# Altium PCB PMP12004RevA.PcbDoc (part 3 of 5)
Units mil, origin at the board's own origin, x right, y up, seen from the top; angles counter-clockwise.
Board outline 5500 x 4500 mil, 6 copper layers (Top Layer, GND, Signal Layer 1, Signal Layer 2, PWR Split, Bottom Layer), stack 0 mil thick; 355 components, 130 nets, 833 pads, 904 vias.
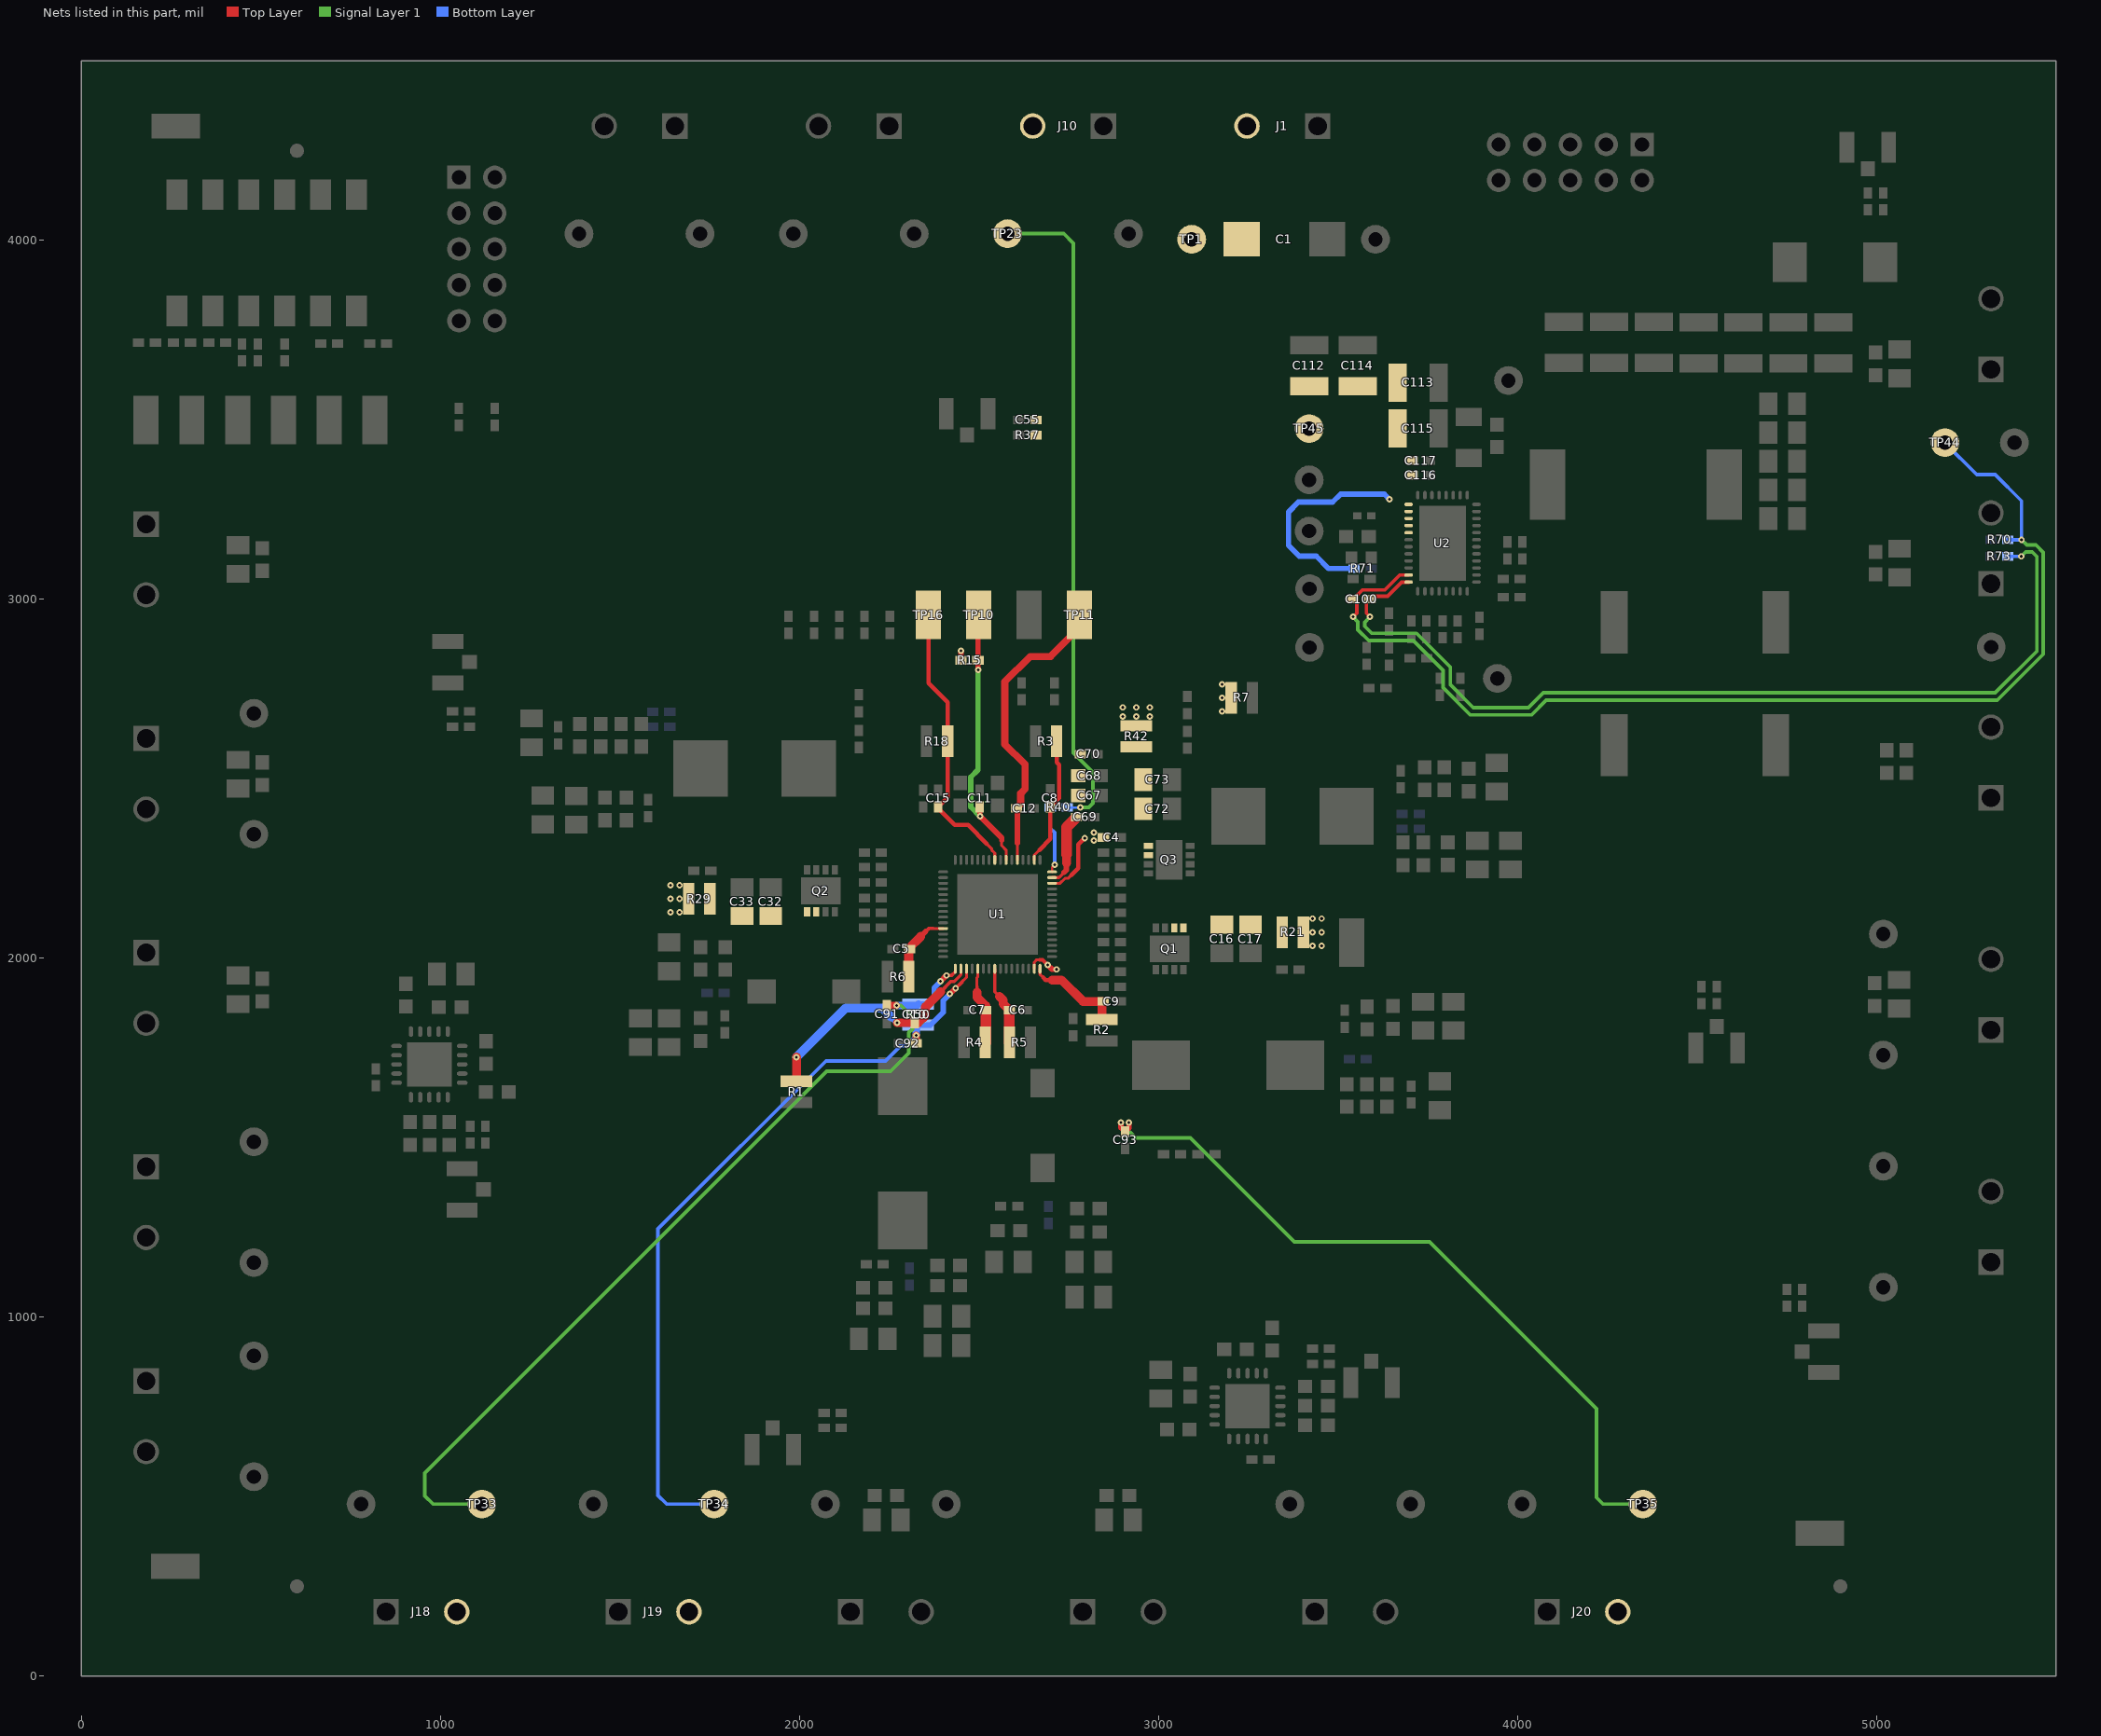
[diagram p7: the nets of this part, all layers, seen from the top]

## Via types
v1: diameter 18, hole 8, Top Layer to Bottom Layer, tented both sides, 835 vias
v2: diameter 19.68, hole 8.01, Top Layer to Bottom Layer, tented bottom, 42 vias
v3: diameter 18, hole 8.01, Top Layer to Bottom Layer, tented bottom, 27 vias

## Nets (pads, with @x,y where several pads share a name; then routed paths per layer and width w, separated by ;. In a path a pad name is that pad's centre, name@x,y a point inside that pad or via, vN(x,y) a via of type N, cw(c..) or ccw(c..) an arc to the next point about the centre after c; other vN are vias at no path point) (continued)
SWA1: C93.1 J20.2 TP35.1 U1.31 | length 2186.4
  Top Layer w8: U1.31@2654.36,1970.89 2654.36,1989.13 2661.07,1995.85 2669.31,1995.85
  Top Layer w10: 2669.31,1995.85 2677.19,1995.85 v1(2691.55,1981.49)
  Top Layer w15: v1(2691.55,1981.49) 2704.12,1968.92 v1(2716.36,1968.92) ; v1(2895.82,1542.6) 2895.82,1528.2 C93.1@2907.42,1516.59 2917.93,1527.11 v1(2917.93,1542.6)
  Signal Layer 1 w10: v1(2917.93,1542.6) 2917.93,1518.97 2937.72,1499.18 3088.85,1499.18 3378.39,1209.64 3755.14,1209.64 4220.11,744.67 4220.11,497.37 4238.48,479 TP35.1@4349.68,479
SWB1: C91.1 J18.2 R50.2 TP33.1 U1.17 | length 2479.3
  Top Layer w8: 2427.02,1955.33 2433.88,1962.19 U1.17@2433.88,1970.89
  Top Layer w10: v1(2409.31,1952.15) 2423.84,1952.15 2427.02,1955.33
  Top Layer w15: v1(2393.18,1936.12) 2393.28,1936.12 v1(2409.31,1952.15)
  Top Layer w20: C91.1@2243.42,1868.22 v1(2270.31,1868.22)
  Signal Layer 1 w10: TP33.1@1115.43,479 979.4,479 956.35,502.05 956.35,565.48 2075.81,1684.94 2253.51,1684.94 2304.61,1736.04 2304.61,1792.51 2314.43,1802.34 2314.43,1836.81 2283.03,1868.22 v1(2270.31,1868.22)
  Bottom Layer w15: R50.2@2330.92,1872.59 2353.74,1872.59 2375.01,1893.87 2375.01,1917.95 v1(2393.18,1936.12)
  Bottom Layer w20: v1(2270.31,1868.22) 2326.54,1868.22 R50.2@2330.92,1872.59
SWB2: C92.1 J19.2 R50.1 TP34.1 U1.19 | length 2137.8
  Top Layer w8: 2452.26,1933.61 2465.38,1946.72 U1.19@2465.38,1970.89
  Top Layer w10: v1(2434.98,1916.32) 2452.26,1933.61
  Top Layer w15: v1@2418.95,1900.29 v1(2434.98,1916.32)
  Top Layer w20: C92.1@2325.42,1762.59 v1(2325.42,1785.58)
  Bottom Layer w10: TP34.1@1762.28,479 1630.53,479 1606.06,503.47 1606.06,1246.03 2073.74,1713.71 2239.86,1713.71 2281.23,1755.08 2294.92,1755.08 v1(2325.42,1785.58)
  Bottom Layer w15: R50.1@2330.92,1813.54 2364.74,1813.54 2400.51,1849.31 2400.51,1881.96 v1(2418.85,1900.29)
  Bottom Layer w20: v1(2325.42,1785.58) 2325.42,1808.04 R50.1@2330.92,1813.54
V5ANA: C15.1 R18.1 TP16.1 U1.57 | length 802.7
  Top Layer w8: 2522.45,2318.5 2535.22,2305.73 2535.22,2301.82 2544.12,2292.92 U1.57@2544.12,2274.04
  Top Layer w12: TP16.1@2359.42,2956.59 2359.42,2766.39 2412.95,2712.86 R18.1@2412.95,2604.59 2412.95,2448.13 C15.1@2386.42,2421.59 2386.42,2417.53 2432.79,2371.16 2469.79,2371.16 2522.45,2318.5
VIN1: C16.1 C17.1 Q1.1 Q1.2 R21.2
VIN2: C32.1 C33.1 Q2.1 Q2.2 R29.2
VIN3: C5.1 R6.2 U1.11 | length 196.4
  Top Layer w8: 2372.69,2083.1 U1.11@2400.42,2083.1
  Top Layer w10: 2351.94,2074.67 2360.36,2083.1 2372.69,2083.1
  Top Layer w15: 2337.83,2060.57 2351.94,2074.67
  Top Layer w25: R6.2@2304.42,1948.59 2304.42,2022.59 C5.1@2307.42,2025.59 ; C5.1@2305.14,2027.88 2337.83,2060.57
VIN4: C6.1 R5.2 U1.24 | length 217.7
  Top Layer w8: 2544.12,1939.57 U1.24@2544.12,1970.89
  Top Layer w10: 2544.12,1939.57 2544.12,1906.64 2553.82,1896.93
  Top Layer w25: 2556.86,1893.71 2567.71,1882.87 2567.71,1872.68 C6.1@2584.8,1855.59
  Top Layer w30: C6.1@2584.8,1855.59 2584.89,1855.5 R5.2@2584.89,1765.59
VIN5: C7.1 R4.2 U1.21 | length 216.3
  Top Layer w8: 2494.62,1920.81 2494.62,1945.73 2496.87,1947.98 U1.21@2496.87,1970.89
  Top Layer w10: 2494.62,1905.38 2494.62,1920.81
  Top Layer w25: 2494.62,1905.38 2494.62,1891.78 2519.04,1867.36 C7.1@2519.04,1855.59
  Top Layer w30: R4.2@2519.04,1765.59 C7.1@2519.04,1855.59
VIN6: C72.1 C73.1 Q3.1 Q3.2 R42.2
VINLDOA2_A3: C8.1 R3.2 U1.50 | length 361.9
  Top Layer w8: U1.50@2654.36,2274.04 2654.36,2287.97 2668.4,2302.02
  Top Layer w12: 2668.4,2302.02 2698.8,2332.41 C8.1@2698.8,2421.97 2723.25,2446.43 2723.25,2539.06 2716.42,2545.89 R3.2@2716.42,2604.59
VINSWA1: C9.1 R2.2 U1.32 | length 270
  Top Layer w8: U1.32@2670.1,1970.89 2670.1,1954.81 2678.74,1946.18
  Top Layer w12: 2678.74,1946.18 2685.35,1939.57 2703.84,1939.57
  Top Layer w25: 2703.84,1939.57 2729.85,1939.57 2789.82,1879.59 2842.42,1879.59 R2.2@2842.42,1829.12
VINSWB: C10.1 R1.2 U1.18 | length 685.7
  Top Layer w8: 2437.49,1941.65 2449.63,1953.79 U1.18@2449.63,1970.89
  Top Layer w10: 2392.86,1906.29 2421.74,1935.18 2431.01,1935.18 2437.49,1941.65
  Top Layer w23: v1(2272.14,1819.97) C10.1@2320.92,1819.97
  Top Layer w25: R1.2@1991.92,1657.29 v1(1991.92,1724.64) ; C10.1@2320.92,1819.97 2330.92,1819.97 2350.9,1839.96 2350.9,1864.34 2392.86,1906.29
  Bottom Layer w18: 2255.92,1836.19 v1(2272.14,1819.97)
  Bottom Layer w25: v1(1991.92,1724.64) 2128.72,1861.45 2230.66,1861.45 2255.92,1836.19
VINVTT: C4.1 R7.2 U1.46 | length 182.2
  Top Layer w8: U1.46@2703.57,2209.08 2726.04,2209.08 2739.43,2222.48 2748.45,2222.48 2757.46,2231.49
  Top Layer w12: 2757.46,2231.49 2776.71,2250.74 2776.71,2316.9 v1(2794.87,2335.05)
  other v1: 2819.74,2327.83 2819.74,2349.95 3177.23,2687.68 3177.23,2725.68 3177.23,2763.68
VOUTS+: C100.1 R70.1 TP44.1 U2.31 | length 3174.1
  Top Layer w10: v1(3542.38,2951.16) 3552.64,2961.42 3552.64,2990.26 C100.1@3542.38,3000.52 3568.19,3026.33 3630.64,3026.33 3672.11,3067.8 U2.31@3696.98,3067.8
  Signal Layer 1 w10: v1(3542.38,2951.16) 3555.76,2937.78 3555.76,2915.44 3585.98,2885.21 3709.96,2885.21 3792.76,2802.41 3792.76,2754.12 3868.65,2678.22 4039.42,2678.22 4080.03,2718.83 5336.66,2718.83 5465,2847.17 5465,3131.2 5444.56,3151.65 5418.86,3151.65 v1(5404.3,3166.2)
  Bottom Layer w10: TP44.1@5191.13,3436.89 5190.73,3436.49 5279.58,3347.63 5331.15,3347.63 5404.3,3274.48 v1(5404.3,3166.2) R70.1@5366.3,3166.2
VOUTS-: C100.2 R73.1 U2.32 | length 2631.6
  Top Layer w10: v1(3589.62,2951.16) 3579.36,2961.42 3579.36,2990.26 C100.2@3589.62,3000.52 3597.89,3008.78 3638.49,3008.78 3677.81,3048.11 U2.32@3696.98,3048.11
  Signal Layer 1 w10: v1(3589.62,2951.16) 3574.94,2936.48 3574.94,2924.96 3594.47,2905.44 3718.54,2905.44 3813.35,2810.63 3813.35,2761.89 3876.69,2698.55 4030.61,2698.55 4072.22,2740.16 5331.44,2740.16 5447.23,2855.95 5447.23,3118.84 5434.11,3131.97 5416.23,3131.97 v1(5404.05,3119.79)
  Bottom Layer w10: R73.1@5366.04,3119.79 v1(5404.05,3119.79)
VREF: C12.1 TP11.1 U1.53 | length 836.7
  Top Layer w8: U1.53@2607.11,2274.04 2607.11,2320.76
  Top Layer w15: C12.1@2604.17,2417.59 2607.11,2414.66 2607.11,2320.76
  Top Layer w20: C12.1@2604.17,2417.59 2616.19,2429.61 2616.19,2459.2 2628.39,2471.4 2628.39,2540.03 2571.86,2596.56 2571.86,2770.27 2642.52,2840.93 2699.11,2840.93 2780.42,2922.24 TP11.1@2780.42,2956.59
VSYS: C1.1 C112.1 C113.1 C114.1 C115.1 C116.1 C117.1 J1.2 R15.2 R21.1 R29.1 R42.1 R71.1 TP1.1 TP45.1 U2.21 U2.22 U2.23 U2.24 U2.25 | length 637.9
  Top Layer w15: R15.2@2450.26,2830.1 v1(2450.26,2856.61)
  Bottom Layer w15: R71.1@3545.31,3085.81 3473.73,3085.81 3439.38,3120.17 3392.48,3120.17 3362.22,3150.43 3362.22,3243.19 3389.86,3270.83 3485.07,3270.83 3507.73,3293.49 3629.06,3293.49 v1(3643.98,3278.57)
  other v1: 3429.35,2034.59 3454.76,2034.59 3429.35,2072.59 3454.76,2072.59 3429.35,2110.59 3454.76,2110.59 1640.55,2127.59 1665.96,2127.59 1640.55,2165.59 1665.96,2165.59 1640.55,2203.59 1665.96,2203.59 2900.42,2673.53 2938.42,2673.53 2976.42,2673.53 2900.42,2698.94 2938.42,2698.94 2976.42,2698.94
VSYS_IN: C11.1 R15.1 TP10.1 U1.55 | length 759.4
  Top Layer w8: 2563.39,2328.93 2563.39,2313.69 2575.62,2301.47 U1.55@2575.62,2274.04
  Top Layer w15: v1(2497.51,2803.6) R15.1@2497.51,2830.1 2497.51,2954.68 TP10.1@2499.42,2956.59 ; C11.1@2502.42,2421.59 2502.42,2396.54 v1(2503.72,2395.24) 2563.39,2335.57 2563.39,2328.93
  Signal Layer 1 w15: v1(2497.51,2803.6) 2497.51,2525.05 2477.21,2504.75 2477.21,2421.75 v1(2503.72,2395.24)
VTT: C55.1 C67.1 C68.1 C69.1 C70.1 J10.2 R37.1 R40.2 TP23.1 U1.47 | length 2062.9
  Top Layer w8: U1.47@2703.57,2224.83 2723.16,2224.83 2737.31,2238.98
  Top Layer w15: 2737.31,2238.98 2743.76,2245.43 2743.76,2265.48
  Top Layer w25: 2743.76,2265.48 2743.76,2289.74
  Top Layer w30: 2743.76,2289.74 2743.76,2364.94 C69.1@2772.42,2393.59
  Signal Layer 1 w10: TP23.1@2579.72,4019 2736.34,4019 2763.06,3992.28 2763.06,2572.6 2817.64,2518.02 2817.64,2432.01 2805.59,2419.97 v1(2782.56,2419.97)
  Bottom Layer w6: R40.2@2746.04,2420.59 2746.67,2419.97 v1(2782.56,2419.97)
VTTFB: R40.1 U1.48 | length 188.1
  Top Layer w6: U1.48@2703.57,2240.58 2703.57,2253.6 v1(2710.98,2261.01)
  Bottom Layer w10: R40.1@2698.8,2420.59 2698.8,2362.62 2710.98,2350.44 v1(2710.98,2261.01)
pads on no net: FID1.1 FID2.1 FID3.1 FID4.1 FID5.1 FID6.1 H1.0 H2.0 H3.0 H4.0 J21.1 J21.2 J21.3 J21.4 J21.5 J21.7 J21.8 J22.1 J22.2 J22.3 J22.4 J22.5

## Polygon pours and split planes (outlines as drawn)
VSYS on Top Layer "GND" (solid, remove dead copper, pour order 145): 3659.26,3194.02 3671.77,3181.51 3707.44,3181.51 3709.63,3183.7 3709.63,3266.65 3700.94,3275.34 3700.94,3305.56 3725.16,3329.79 3725.16,3637.5 3698.21,3664.45 3354.78,3664.45 3337.92,3681.3 3337.92,4469.8 3044.92,4469.8 3044.92,3610.54 3098.57,3556.88 3098.57,2952.81 2872.99,2726.84 2872.99,2641.63 2884.32,2630.3 2984.01,2630.3 2995.68,2641.97 2995.68,2692.42 3345.08,3041.82 3345.08,3365.82 3383.62,3404.35 3454.65,3404.35 3659.26,3199.74
GND on Top Layer "Top Layer-No Net" (solid, remove dead copper, pour order 100): 3555,3099.83 3489.13,3099.84 3472,3116.97 3472,3198.34 3478.7,3205.03 3550.52,3205.03 3555,3200.55
GND on Top Layer "GND" (solid, remove dead copper, pour order 126): 3856.69,1507.47 3856.69,1600.24 3844.34,1612.6 3497.06,1612.6 3475.67,1591.21 3468.36,1583.9 3468.36,1497.31 3508.58,1457.08 3807.06,1457.08
GND on Top Layer "GND" (solid, remove dead copper, pour order 133): 2697.63,529.05 2847.26,529.05 2872.71,529.05 2881.2,520.56 2881.2,188.65 2831.1,138.55 2727.01,138.55 2665.7,199.87 2665.7,497.43
BUCK5_OUT on Top Layer "GND" (solid, remove dead copper, pour order 150): 1902.46,1581.84 1902.46,1494.54 1902.46,1382.7 2070.94,1214.22 2182.77,1214.22 2217.2,1179.8 2217.2,865.86 2099.95,748.61 2099.95,670 2249.86,520.09 2249.86,296.53 2249.86,3.31 2248.8,2.25 3110.34,2.25 3112.49,0.1 3112.49,380.69 2642.21,850.96 2434.2,850.96 2407.6,877.55 2407.61,1102.05 2407.61,1326.49 2116.46,1617.63 1938.24,1617.63
GND on Top Layer "GND" (solid, remove dead copper, pour order 122): 2088.43,846.37 2184.62,846.37 2202.22,863.97 2202.22,1170.28 2171.9,1200.6 2070.93,1200.6 2051.53,1181.2 2051.53,882.73
GND on Top Layer "GND" (solid, remove dead copper, pour order 130): 2423.87,1313.12 2423.87,885.89 2443.25,866.5 2550.24,866.5 2577.31,893.57 2577.31,1354.39 2568.6,1363.1 2473.85,1363.1
GND on Top Layer "GND" (solid, remove dead copper, pour order 125): 2917.39,1388.13 2824.61,1388.13 2812.25,1375.77 2812.25,1028.49 2833.64,1007.1 2840.95,999.79 2927.54,999.79 2967.77,1040.02 2967.77,1338.49
GND on Top Layer "GND" (solid, remove dead copper, pour order 121): 3491.94,1923.55 3491.94,1845.69 3499.17,1838.45 3856.69,1838.45 3872.96,1854.72 3880.27,1862.03 3880.27,1948.62 3851.71,1977.19 3544.78,1977.19
BUCK1_OUT on Top Layer "GND" (solid, remove dead copper, pour order 148): 3234.51,1793.48 3234.51,1661.43 3270.25,1625.69 3870.24,1625.69 4434.54,1061.4 4851.52,1061.4 5040.68,1250.56 5495.31,1250.56 5495.31,1599.68 5496.94,1601.32 4357.19,1601.32 4213.07,1745.43 4132.53,1825.97 3266.9,1825.97
GND on Top Layer "GND" (solid, remove dead copper, pour order 124): 4024.32,2179.54 4024.32,2272.31 4011.96,2284.67 3664.68,2284.67 3643.29,2263.28 3635.98,2255.97 3635.98,2169.38 3676.21,2129.15 3974.68,2129.15
GND on Top Layer "GND" (solid, remove dead copper, pour order 123): 3640.18,2619.97 3640.18,2523.78 3657.51,2506.45 3972.84,2506.45 3989.88,2523.49 3989.88,2642 3969.9,2661.98 3681.56,2661.98
BUCK6_OUT on Top Layer "GND" (solid, remove dead copper, pour order 147): 3239.04,2778.06 3239.04,2683.06 3333,2589.1 3367.08,2555.02 3367.08,2424.92 3367.08,2341.28 3409.28,2299.07 4041.3,2299.07 4269.4,2070.97 4434.48,1905.88 5500.86,1905.88 5500.86,2311.74 5500.25,2312.35 4537.01,2312.35 4358.69,2490.66 3649.88,2490.66 3618.02,2522.52 3618.02,2619.35 3446.24,2791.12 3252.07,2791.12
GND on Top Layer "GND" (solid, remove dead copper, pour order 108): 2802.08,2405.16 2802.08,2381.54 2808.23,2375.39 2858.69,2375.39 2888.56,2405.26 2888.56,2547.39 2869.65,2566.3 2869.65,2602.14 2863,2608.79 2834.34,2608.79 2822.11,2608.79 2814.83,2601.51 2814.83,2417.93
VTT on Top Layer "GND" (solid, remove dead copper, pour order 144): 2780.63,2363.32 2788.14,2370.82 2788.14,2409.4 2799.66,2420.92 2799.66,2712.46 3030.72,2943.52 3030.72,3092.77 3030.72,3492.5 2770,3753.22 2770,4500.99 2423,4500.99 2423,3751.17 2642.75,3531.42 2642.75,3276.1 2847.39,3071.47 2847.39,2869.7 2741.85,2764.17 2741.85,2394.86 2741.85,2382.66 2761.2,2363.32
GND on Top Layer "GND" (solid, remove dead copper, pour order 119): 1465.35,1761.43 1493.37,1789.45 1742.64,1789.45 1761.89,1808.7 1763.63,1810.45 1803.13,1810.45 1818.41,1810.45 1829.32,1799.53 1834.99,1793.86 1834.99,1769.2 1834.99,1712.87 1812.52,1690.4 1784.1,1661.97 1601.41,1661.97 1479.13,1661.97 1465.6,1675.51
GND on Top Layer "GND" (solid, remove dead copper, pour order 112): 1554.83,2102.62 1714.53,2102.62 1762.28,2054.87 1889.81,2054.88 1897.66,2047.03 1897.66,2016.3 1889.22,2007.86 1562.79,2007.86 1536.74,2033.9 1536.74,2084.53
GND on Top Layer "GND" (solid, remove dead copper, pour order 120): 1213.37,2390.53 1233.23,2410.4 1605.58,2410.4 1618.87,2397.11 1618.87,2347.54 1548.79,2277.45 1253.02,2277.45 1213.43,2317.05
GND on Top Layer "GND" (solid, remove dead copper, pour order 127): 1169.78,2750.57 1169.78,2673.07 1214.2,2628.65 1562.55,2628.65 1595.56,2628.65 1616.36,2649.45 1616.36,2754.83 1594.2,2776.99 1196.2,2776.99
GND on Top Layer "GND" (solid, remove dead copper, pour order 138): 102.06,3332.54 102.06,3189.52 171,3120.58 525.45,3120.58 542.3,3137.43 542.3,3325.5 478.49,3389.31 158.83,3389.31
GND on Top Layer "GND" (solid, remove dead copper, pour order 137): 102.06,2705.14 102.06,2592.67 176.51,2518.22 528.54,2518.22 542.3,2531.98 542.3,2704.24 484.38,2762.16 159.08,2762.16
GND on Top Layer "GND" (solid, remove dead copper, pour order 136): 102.06,2108.4 102.06,1995.82 176.51,1921.37 528.54,1921.37 542.3,1935.13 542.3,2031.23 412.47,2161.06 154.72,2161.06
BUCK1_OUT on Top Layer "GND" (solid, remove dead copper, pour order 93): 2681.86,1716.6 2665.78,1700.51 2630.23,1700.52 2623.05,1707.7 2623.05,1807.81 2631.97,1816.74 2674.18,1816.74 2681.22,1809.69
BUCK1_OUT on Top Layer "GND" (solid, remove dead copper, pour order 92): 2420.45,1716.6 2436.53,1700.51 2472.08,1700.52 2479.26,1707.7 2479.26,1807.81 2472.45,1814.62 2429.05,1814.62 2421.06,1806.63
BUCK1_OUT on Top Layer "GND" (solid, remove dead copper, pour order 99): 2181.23,1905 2186.07,1900.16 2188.95,1897.28 2212.66,1897.28 2257.92,1897.28 2263.7,1903.05 2263.7,1993.38 2257.34,1999.74 2186.74,1999.74 2181.85,1994.84
BUCK5_OUT on Top Layer "GND" (solid, remove dead copper, pour order 96): 2619.45,2653.59 2635.53,2669.67 2671.08,2669.67 2680.4,2660.35 2680.4,2544.05 2674.64,2538.29 2658.99,2538.29 2619.97,2577.31
BUCK1_OUT on Top Layer "GND" (solid, remove dead copper, pour order 94): 2315.98,2653.59 2332.07,2669.67 2367.61,2669.67 2374.8,2662.49 2374.8,2562.37 2365.88,2553.45 2323.66,2553.45 2316.62,2560.49
LX3 on Top Layer "GND" (solid, remove dead copper, pour order 111): 2170.22,1874.15 2164.74,1868.67 2048.85,1868.67 2026.08,1891.44 2026.08,2012.77 2057.92,2044.61 2152.61,2044.61 2170.22,2027.01
LX4 on Top Layer "GND" (solid, remove dead copper, pour order 109): 2683.41,1691.07 2643.78,1691.07 2618.8,1666.09 2618.8,1600.46 2635.44,1583.82 2754.29,1583.82 2774.44,1603.96 2774.44,1714.45 2727.89,1761 2703.64,1761.01 2693.52,1750.89 2693.52,1701.19
LX5 on Top Layer "GND" (solid, remove dead copper, pour order 118): 2405.15,1577.84 2375.77,1548.46 2233.35,1548.46 2192.58,1589.23 2192.58,1711.91 2216.02,1735.35 2345.57,1735.35 2364.55,1754.33 2364.55,1816.4 2370.99,1822.84 2392.49,1822.84 2405.15,1810.19
VIN2 on Top Layer "GND" (solid, remove dead copper, pour order 114): 1729.47,2206.39 1729.47,2112.56 1771.75,2070.28 1991.76,2070.28 2021.56,2070.28 2057.73,2106.45 2057.91,2139.61 1988.65,2139.61 1976.6,2151.66 1801.84,2151.66 1788.49,2165.01 1788.49,2203.67 1781.09,2211.07 1734.14,2211.07
VSYS on Top Layer "GND" (solid, remove dead copper, pour order 98): 1627.25,2125.38 1634.59,2118.04 1705.57,2118.04 1709.7,2122.17 1709.7,2210.38 1703.34,2216.74 1632.74,2216.74 1627.85,2211.84
GND on Top Layer "GND" (solid, remove dead copper, pour order 117): 1796.48,2269.15 1796.48,2174.74 1808.11,2163.12 1809.53,2161.7 1969.47,2161.7 1980.39,2161.7 1992.37,2149.72 1993.77,2148.32 2100.54,2148.32 2120.27,2148.32 2130.14,2158.19 2130.14,2172.98 2121.33,2181.79 2121.67,2217.74 2121.67,2221.31 2115.41,2227.57 2002.97,2227.57 1990.81,2239.73 1990.81,2261.63 1981.92,2270.51 1975.26,2277.18 1804.51,2277.18
NetL2_1 on Top Layer "GND" (solid, remove dead copper, pour order 131): 1920.95,2600.68 1920.95,2353.17 2006.1,2268.01 2006.1,2240.37 2014.36,2232.12 2082.22,2232.12 2083.98,2233.88 2083.98,2272.01 2128.65,2316.69 2128.65,2499.39 2186.44,2557.17 2186.44,2600.47 2178.43,2608.47 2138.23,2608.47 2117.32,2629.39 1949.66,2629.39
BUCK1_OUT on Top Layer "GND" (solid, remove dead copper, pour order 95): 2891.41,1732.15 2907.5,1748.24 2907.5,1783.78 2900.31,1790.97 2800.2,1790.97 2791.28,1782.04 2791.28,1739.83 2798.32,1732.79
NetL1_1 on Top Layer "GND" (solid, remove dead copper, pour order 134): 3007.73,1981.37 3007.73,1927.79 2923.13,1843.2 2923.13,1600.84 2951.01,1572.96 2951.01,1461.47 2981.86,1430.62 3026.89,1430.62 3034.43,1438.16 3036.58,1440.31 3036.58,1465.98 3036.58,1477.46 3123.58,1564.47 3123.59,1924.26 3123.58,1931.44 3073.86,1981.17
GND on Top Layer "GND" (solid, remove dead copper, pour order 115): 3294.53,1944.77 3294.53,2039.18 3281.48,2052.22 3110.62,2052.22 3098.64,2064.2 2969.34,2064.2 2960.87,2055.73 2960.87,2040.94 2969.68,2032.13 2969.34,1996.18 2969.34,1992.61 2975.6,1986.35 3088.04,1986.35 3137.65,1936.74 3286.5,1936.74
VIN1 on Top Layer "GND" (solid, remove dead copper, pour order 113): 3034.94,2108.92 3034.94,2071.7 3036.14,2070.49 3102.89,2070.49 3110.28,2063.11 3112.24,2061.15 3204.9,2061.15 3287.07,2061.15 3305.12,2043.1 3329.5,2018.72 3363.26,2018.72 3370.41,2025.87 3370.41,2070.52 3370.41,2118.34 3351.34,2137.4 3077.78,2137.4 3063.29,2122.91 3049.04,2122.91
VSYS on Top Layer "GND" (solid, remove dead copper, pour order 97): 3468.06,2112.81 3460.72,2120.15 3389.74,2120.15 3385.61,2116.02 3385.61,2027.81 3391.97,2021.45 3462.57,2021.45 3467.46,2026.35
GND on Top Layer "GND" (solid, remove dead copper, pour order 116): 3111.21,2536.5 3016.8,2536.5 3003.76,2523.46 3003.76,2352.6 2991.78,2340.62 2991.78,2211.31 3000.24,2202.85 3015.04,2202.85 3023.85,2211.65 3059.8,2211.31 3063.36,2211.31 3069.63,2217.58 3069.63,2330.02 3119.24,2379.62 3119.24,2528.48
VINVTT on Top Layer "GND" (solid, remove dead copper, pour order 90): 2783.72,2338.25 2783.72,2326.22 2787.08,2322.86 2794.27,2315.67 2821.01,2315.67 2824.98,2319.64 2853.89,2319.64 2858.26,2319.64 2862.74,2324.12 2862.74,2348.75 2851.37,2360.12 2830.07,2360.12 2805.59,2360.12
GND on Top Layer "GND" (solid, remove dead copper, pour order 89): 2878.36,2365.25 2878.36,2322.96 2886.67,2314.65 2927.25,2314.65 2933.62,2321.02 2933.62,2350.72 2933.62,2354.3 2916.52,2371.4 2915.09,2372.83 2885.94,2372.83
VIN6 on Top Layer "GND" (solid, remove dead copper, pour order 110): 2948.5,2287.11 2958.61,2277.01 2979.32,2277.01 2979.32,2349.72 2988.54,2358.94 2988.54,2603.85 2983.68,2608.71 2891.48,2608.71 2885.13,2602.36 2885.13,2573.12 2903.73,2554.52 2903.73,2405.69 2948.75,2360.66
NetL4_1 on Top Layer "GND" (solid, remove dead copper, pour order 132): 3074.66,2313.82 3074.66,2259 3078.29,2255.37 3293.97,2255.37 3342.78,2304.18 3342.78,2544.19 3279.3,2607.67 3067.04,2607.67 3059.33,2599.95 3059.33,2561.08 3066.59,2553.81 3121.37,2553.81 3134.93,2540.25 3134.93,2373.99
VINVTT on Top Layer "GND" (solid, remove dead copper, pour order 91): 3164.76,2769.48 3175.73,2780.46 3215.24,2780.46 3223.54,2772.16 3223.54,2683.46 3214.62,2674.54 3172.41,2674.54 3165.36,2681.58
LDO3P3 on Top Layer "GND" (solid, remove dead copper, pour order 149): 1392.57,2932.63 2270.46,2932.63 2288.73,2950.9 2288.73,3011.82 2317.16,3040.25 2342.34,3065.42 2484.88,3065.42 2527.51,3065.42 2565.28,3027.66 2565.28,2912.73 2601.02,2877 2603.05,2874.97 2690.77,2874.97 2715.13,2899.33 2715.13,2979.33 2715.13,3076.74 2288.97,3502.9 1062.23,3502.9 1020.26,3502.9 976.83,3459.48 976.83,3230.79 1274.85,2932.77
GND on Top Layer "GND" (solid, remove dead copper, pour order 153): 0,0 5500,0 5500,4500 0.8,4500 0.51,4500.29
NetC109_2 on Top Layer "GND" (solid, remove dead copper, pour order 139): 4100,3135 4007.04,3135 4001.52,3140.52 3996.3,3145.74 3996.31,3175.74 3991.52,3180.52 3899,3180.52 3877,3180.52 3873,3184.52 3873,3267.52 3916,3310.52 3916,3363.52 3916,3437.52 3932,3453.52 3968,3453.52 3980,3465.52 3980,3510 3910,3580 3910,3640 3950,3680 4010,3680 4160,3530 4160,3195
GND on Top Layer "GND" (solid, remove dead copper, pour order 105): 3216.96,678.62 3278.11,678.62 3282.59,674.13 3282.59,537.09 3271.61,526.11 3228.88,526.11 3222.22,532.76 3213.09,541.9 3213.09,674.77
LDO3P3 on Top Layer "GND" (solid, remove dead copper, pour order 102): 3065.36,708.87 3169.32,708.87 3174.1,704.09 3174.1,636.97 3162.69,625.56 3158.98,621.85 3095.3,621.85 3068.24,621.85 3058.16,631.93 3054.98,635.11 3054.98,677.56 3054.98,698.55
GND on Top Layer "GND" (solid, remove dead copper, pour order 104): 3271.36,822.76 3225.89,822.76 3214.92,833.73 3214.92,967.4 3214.92,976.49 3222.95,984.52 3275.58,984.52 3279.76,980.34 3279.76,831.15
GND on Top Layer "GND" (solid, remove dead copper, pour order 103): 1204.82,1727.16 1204.82,1681.69 1195.17,1672.04 1049.78,1672.04 1043.07,1678.75 1043.06,1731.38 1047.24,1735.55 1196.43,1735.55
LDO3P3 on Top Layer "GND" (solid, remove dead copper, pour order 101): 925.64,1887.05 925.64,1783.08 920.87,1778.3 853.74,1778.3 842.33,1789.71 838.62,1793.42 838.62,1857.1 838.62,1884.16 848.7,1894.24 851.89,1897.43 894.33,1897.43 915.32,1897.43
GND on Top Layer "GND" (solid, remove dead copper, pour order 106): 895.39,1735.45 895.39,1674.29 890.91,1669.81 753.86,1669.81 742.88,1680.79 742.88,1723.52 749.54,1730.18 758.67,1739.32 891.54,1739.32
BUCK3_OUT on Top Layer "GND" (solid, remove dead copper, pour order 142): 1021.78,2114.16 942.85,2035.23 942.85,1889.52 942.85,1848.81 951.84,1839.82 960.2,1831.46 960.2,1784.61 966.89,1777.92 1012.06,1777.92 1038.91,1777.92 1043.01,1773.82 1043.02,1750.82 1046.53,1747.3 1122.32,1747.3 1427.99,1747.3 1476,1795.32 1487.16,1806.48 1545.69,1806.48 1738.7,1806.48 1751.49,1819.27 1754.76,1822.54 1790.69,1822.54 1901.53,1822.54 1939.49,1860.5 1939.49,1949.01 1900.15,1988.34 1892.18,1996.31 1548.86,1996.31 1431.01,2114.16
NetC131_1 on Top Layer "GND" (solid, remove dead copper, pour order 146): 960.56,1628.75 960.56,1585.42 945.28,1570.13 945.28,1528.33 958.78,1514.82 1047.44,1514.82 1106.7,1514.82 1120.05,1501.47 1120.05,1374.64 1120.82,1373.87 1091.42,1344.46 41.29,1344.46 -0.82,1344.46 -1.04,959.89 -1.41,959.51 1468.29,959.51 1604.36,1095.58 1604.36,1512.65 1454.5,1662.51 1053,1662.51 1049.63,1662.51 1042.91,1655.79 1042.91,1633.88 1040.61,1631.58 963.39,1631.58
BUCK4_OUT on Top Layer "GND" (solid, remove dead copper, pour order 141): 2587.24,1453.77 2587.24,932.09 2757.99,761.34 2798.69,720.65 3098.69,720.65 3122.31,744.26 3149.92,744.26 3168.8,744.26 3174.04,749.51 3174.04,815.32 3184.59,825.87 3185.47,826.75 3201.32,826.75 3204.54,829.98 3204.54,910.07 3204.54,971.97 3185.47,991.04 2834.45,991.04 2800.89,1024.6 2798.86,1026.62 2798.86,1163.48 2798.86,1445.72 2760.11,1484.47 2618.06,1484.47
NetC145_1 on Top Layer "GND" (solid, remove dead copper, pour order 143): 3287.21,1090 3287.21,834.32 3294.9,826.63 3312.92,826.63 3317.11,822.44 3323.2,816.36 3323.2,804.44 3323.2,746.24 3326.93,742.5 3361.53,742.5 3373.68,730.35 3428.84,730.35 3436.32,737.83 3440.99,742.5 3440.99,870.58 3440.99,883.65 3449.35,892.01 3451.28,893.94 3518.97,893.94 3536.95,875.96 3536.95,2.33 3535.25,0.63 3918.12,0.63 3918.34,1008.26 3769.77,1156.83 3354.05,1156.84
NetC97_1 on Top Layer "GND" (solid, remove dead copper, pour order 152): 4070,3700 4070,3635 4180,3525 4180,2840 4220,2800 4275,2745 4750,2745 4940.15,2554.85 5505,2554.85 5505,4104.36 4962.07,4104.36 4945,4087.3 4945,3735 4930,3720 4090,3720
GND on Top Layer "GND" (solid, remove dead copper, pour order 129): 4977.82,3099.23 5453.51,3099.23 5469.71,3083.02 5469.71,2966.33 5458.1,2954.72 4980,2954.72 4965,2969.72 4960,2974.72 4960,3080.61
GND on Top Layer "GND" (solid, remove dead copper, pour order 107): 5003.89,2546.17 5107.45,2546.17 5129.11,2524.5 5129.11,2467.93 5101.18,2440 5003.54,2440 4978,2465.54 4978,2519.13
GND on Top Layer "GND" (solid, remove dead copper, pour order 140): 4195,2700 4210,2715 4750,2715 4795,2670 4795,2525 4770,2500 4220,2500 4195,2525
GND on Top Layer "GND" (solid, remove dead copper, pour order 128): 4744.03,3572.32 4744.03,3183.5 4752.53,3175 4850,3175 4885,3175 4910,3200 4910,3525 4910,3565 4885,3590 4761.71,3590
GND on Top Layer "Top Layer-No Net" (solid, pour order 135): 5100.7,3514.7 5472.05,3514.7 5482.61,3525.26 5488.5,3531.15 5488.5,3626.09 5488.5,3708.29 5472.05,3724.74 5256.43,3724.74 5189.11,3657.42 5179.8,3648.11 5094.79,3648.11 4983.1,3648.11 4976.28,3641.29 4976.28,3532.69 4994.27,3514.7
BUCK2_OUT on Top Layer "GND" (solid, remove dead copper, pour order 151): -0.01,3105.55 594.41,3105.55 987.76,2712.21 1042.9,2712.2 1049.6,2705.51 1049.6,2630.11 1063.16,2616.55 1234.73,2616.55 1798.12,2616.55 1808.63,2606.04 1808.63,2454.57 1785.95,2431.89 1780.8,2426.74 1215.17,2426.74 533.69,1745.26 -1.49,1745.26
LDO3P3 on Bottom Layer "GND" (solid, remove dead copper, pour order 175): 148.74,3573.81 142.22,3697.04 142.22,3743.22 194.27,3795.27 473.42,3795.27 484.2,3784.49 489.69,3779 489.69,3711.9 489.69,3698.7 505.09,3683.3 539.18,3683.3 553.48,3697.6 556.23,3700.35 556.23,3741.04 556.23,3778.43 572.74,3794.94 846.15,3795.36 1167.16,3474.35 1179.79,3461.72 1179.79,3395.04 1110.62,3325.87 554.48,3325.87 449.75,3430.6 442.63,3437.71 293.29,3437.71 284.84,3437.71
GND on Bottom Layer "GND" (solid, remove dead copper, pour order 176): 0,0 5500,0 5500,4500 0.8,4500 0.51,4500.29
BUCK2_OUT on PWR Split "GND" (solid, remove dead copper, pour order 173): 2.92,1733.64 469.1,1733.64 695.66,1960.19 706.55,1971.08 1129.16,1971.08 1689.01,2530.93 1689.01,2864.25 1545.24,3008.01 1455.93,3097.33 -1.44,3097.33
SWB1 on PWR Split "GND" (solid, remove dead copper, pour order 167): 2430.24,1954.54 2430.24,1994.23 2375.86,2048.61 2314.64,2048.61 2311.91,2048.61 2282.32,2019.03 1740.58,1477.28 1642.19,1477.28 1600.41,1477.28 1554.32,1431.19 912.34,789.21 912.34,0.87 1380.41,0.87 1383.71,-2.44 1383.71,908.01
LDOA1 on PWR Split "GND" (solid, remove dead copper, pour order 172): 30.3,754.38 460.95,754.38 1815.74,2109.17 2292.24,2109.17 2304.23,2097.17 2304.23,2051.53 2258.49,2005.79 1739.76,1487.06 1595.5,1487.06 893.24,784.8 893.24,188.04 893.24,0.38 7,0.38 -0.92,8.29 -0.92,753.23 0.29,754.44
SWB2 on PWR Split "GND" (solid, remove dead copper, pour order 169): 2372.38,1880.72 2421.56,1929.9 2477.7,1929.9 2519.96,1887.64 2539.48,1868.12 2539.48,1843.21 2539.48,1747.12 2459.73,1667.37 1920.34,1127.98 1920.34,256.28 1920.34,0.75 1402.79,0.47 1402.31,-0.01 1402.31,898.34 2372.33,1868.36 2372.33,1872.02
LDOA2 on PWR Split "GND" (solid, remove dead copper, pour order 170): 2576.08,2285.75 2649.72,2285.75 2673.44,2309.47 2673.44,2661.77 2654.62,2680.59 2654.62,2892.98 1958.67,3588.93 1772.62,3774.98 1772.62,4502.33 1322.16,4502.33 1322.16,3810.98 2369.47,2763.67 2539.24,2593.9 2539.24,2322.59
SWA1 on PWR Split "GND" (solid, remove dead copper, pour order 171): 2655.42,1993.86 2655.42,1835.48 2830.09,1660.81 2831,1659.9 2831,1622 2831,1580.93 2892.63,1519.3 4149.32,262.61 4149.32,-0.02 4624.44,-0.02 4624.66,0.21 4624.66,531.57 4054.42,1101.81 3854.4,1101.81 2937.36,2018.85 2679.63,2018.85 2655.05,1994.27
DRV5V_1_6 on PWR Split "GND" (solid, remove dead copper, pour order 163): 2807.07,2064.79 2837.09,2034.77 2951.3,2034.77 3168.84,2034.77 3274.87,1928.75 3278.8,1924.81 3332.63,1924.81 3338.32,1924.81 3369.82,1956.31 3369.82,2087.61 3319.06,2138.36 3317.98,2139.45 2823.78,2139.45 2806.99,2122.63
DRV5V_2_A1 on PWR Split "GND" (solid, remove dead copper, pour order 164): 1750.95,2269.9 1750.95,2213.68 1768.22,2196.4 1843.39,2121.24 2298.13,2121.24 2316.87,2139.98 2316.87,2224.07 2183.75,2357.19 1881.77,2357.19 1838.24,2357.19
LDOA3 on PWR Split "GND" (solid, remove dead copper, pour order 168): 2672.77,2265.39 2672.77,2290.42 2689.52,2307.18 2689.52,2658.9 2674.01,2674.42 2663.76,2684.67 2663.76,2770.53 2663.76,2905.32 2546.71,3022.36 1789.14,3779.94 1789.14,4500.63 2187.61,4500.63 2187.69,3904.64 2475.54,3616.78 2824.59,3267.73 2824.59,2455.49 2768.38,2399.28 2768.38,2305.5 2716.69,2253.8 2684.36,2253.8
VINVTT on PWR Split "GND" (solid, remove dead copper, pour order 165): 2779.89,2323.46 2793.62,2309.72 2995.5,2309.72 3224.45,2538.67 3224.45,2707.39 3224.45,2777.02 3202.46,2799.01 3197.57,2803.9 3131.61,2803.9 3069.31,2803.9 3025.33,2759.92 3011.89,2746.49 3011.89,2660.97 3011.89,2624.85 2781,2393.96
LDO5V on PWR Split "GND" (solid, remove dead copper, pour order 166): 1597.92,2208.04 1728.79,2208.04 1741.18,2220.43 1741.18,2269.31 1741.18,2274.13 1771.48,2304.43 1831.38,2364.33 1867.18,2364.33 2190.09,2364.33 2308.51,2245.9 2485.14,2069.28 2654.43,2069.28 2730.64,2069.28 2806.7,2145.34 2807.43,2146.07 2969.48,2146.07 3324.06,2146.07 3352.29,2117.84 3378.44,2091.69 3378.44,2075.14 3378.44,1956.05 3406.68,1927.81 3422.52,1911.98 3625.63,1911.98 3644.22,1930.57 3644.22,2143.32 3644.22,2201.13 3518.9,2326.45 3025.24,2326.45 3003.22,2304.43 2786.34,2304.43 2739.52,2257.61 2727.13,2245.22 2688.57,2245.22 2676.18,2245.22 2658.96,2262.43 2645.88,2275.51 2597.69,2275.51 2573.59,2275.51 2550.18,2298.92 2530.2,2318.89 2530.2,2367.78 2530.2,2591.54 2513,2608.75 2475.82,2645.93 2256.88,2645.93 1816.23,2645.93 1688.86,2518.55 1570.75,2400.44 1570.74,2235.21
GND on PWR Split "GND" (solid, remove dead copper, pour order 174): 0,0 5500,0 5500,4500 0.8,4500 0.51,4500.29
NetC97_1 on Signal Layer 2 "GND" (solid, remove dead copper, pour order 160): 5499.41,2566.5 4271.84,2566.51 4253.75,2584.6 4247.62,2590.72 4247.62,3175.24 4247.62,4499.91 4248.84,4501.12 5502.45,4501.12 5504.89,4498.68
BUCK5_OUT on Signal Layer 2 "GND" (solid, remove dead copper, pour order 157): 1697.51,2410.09 1697.51,1854.16 1828.37,1723.3 1828.37,1326.58 1937.85,1217.1 2208.61,1217.1 2250.98,1259.48 2250.98,1690.33 2143.86,1797.46 2136.8,1804.52 2136.8,1982.28 2136.8,2543.8 2182.71,2589.71 2282.85,2689.86 2478.67,2689.86 2514.26,2654.26 2519.67,2648.85 2519.67,2598.86 2519.67,2537.25 2535.09,2521.83 2720.83,2521.83 2744.98,2545.98 2772.04,2573.04 2772.04,2710.06 2772.04,2724.23 2719.16,2777.11 2665.01,2831.26 2550.9,2831.26 2110.79,2831.26 1886.46,2606.94
BUCK1_OUT on Signal Layer 2 "GND" (solid, remove dead copper, pour order 159): 2152.55,1812.46 2682.23,1282.79 5493.81,1282.79 5499.96,1282.79 5500.1,1733.54 5499.52,1734.12 3055.39,1734.12 2638.5,2151.01 2505.86,2283.65 2505.86,2645.4 2481.08,2670.18 2287.06,2670.18 2152.55,2535.68
VSYS on Signal Layer 2 "GND" (solid, remove dead copper, pour order 161): 1453.54,2104.43 1661.49,2104.43 1694.46,2137.4 1694.46,2174.68 1694.46,2418.85 1866.59,2590.98 2115.01,2839.4 2460.86,2839.4 2663.91,2839.4 2737.54,2765.77 2869.2,2634.11 2971.84,2634.11 3353.2,2252.75 3353.2,2063.78 3412.72,2004.27 3556.38,2004.27 3966.85,2004.27 4159.77,2197.19 4242.41,2279.82 4242.41,4496.97 3006.76,4496.97 3006.76,3375.27 2924.93,3293.44 1941.06,3293.44 1437.54,2789.92 1437.54,2120.48
GND on Signal Layer 2 "GND" (solid, remove dead copper, pour order 162): 0,0 5500,0 5500,4500 0.8,4500 0.51,4500.29
LDO3P3 on Signal Layer 2 "GND" (solid, remove dead copper, pour order 158): 814.33,1886.63 828.91,1901.21 1014.72,1901.21 1160.9,1755.02 1219.98,1695.94 1219.98,1288.22 1662.59,845.6 2838.92,845.6 3025.32,1032 3279.31,1032 3373.09,938.22 3373.09,690.19 3330.2,647.3 3293.99,611.09 3083.15,611.09 1149.76,611.09 814.33,946.52
GND on Signal Layer 1 "GND" (solid, remove dead copper, pour order 156): 0,0 5500,0 5500,4500 0.8,4500 0.51,4500.29
LDO3P3 on Signal Layer 1 "GND" (solid, remove dead copper, pour order 155): -0.03,3818.47 747.03,3818.47 820.16,3745.34 820.16,3650.32 760.24,3590.4 287.44,3590.4 220.29,3590.4 149.72,3519.83 149.72,2378.08 267.94,2259.86 303.24,2224.56 783.19,2224.56 1042.83,1964.92 1042.82,1866.23 953.56,1776.97 -0.21,1776.97
GND on GND "GND" (solid, remove dead copper, pour order 154): 0,0 5500,0 5500,4500 0.8,4500 0.51,4500.29

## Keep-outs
Keep-Out Layer:
  lines w10: -5,-5.11 -5,4505 ; -5,-5 5505,-5 5505,4505.11 -5,4505.11
  text ".Layer_Name" at 577,-858.49 h60

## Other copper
Top Layer:
  pour cut-out: 1335.59,4019 1337.31,4032.05 1342.35,4044.22 1350.36,4054.66 1360.81,4062.67 1372.97,4067.71 1386.02,4069.43 1399.08,4067.71 1411.24,4062.67 1421.69,4054.66 1429.7,4044.22 1434.74,4032.05 1436.46,4019 1434.74,4005.95 1429.7,3993.78 1421.69,3983.34 1411.24,3975.33 1399.08,3970.29 1386.02,3968.57 1372.97,3970.29 1360.81,3975.33 1350.36,3983.34 1342.35,3993.78 1337.31,4005.95
  pour cut-out: 1672.44,4019 1674.16,4032.05 1679.2,4044.22 1687.21,4054.66 1697.66,4062.67 1709.82,4067.71 1722.87,4069.43 1735.93,4067.71 1748.09,4062.67 1758.54,4054.66 1766.55,4044.22 1771.59,4032.05 1773.31,4019 1771.59,4005.95 1766.55,3993.78 1758.54,3983.34 1748.09,3975.33 1735.93,3970.29 1722.87,3968.57 1709.82,3970.29 1697.66,3975.33 1687.21,3983.34 1679.2,3993.78 1674.16,4005.95
  pour cut-out: 1932.44,4019 1934.16,4032.05 1939.2,4044.22 1947.21,4054.66 1957.66,4062.67 1969.82,4067.71 1982.87,4069.43 1995.93,4067.71 2008.09,4062.67 2018.54,4054.66 2026.55,4044.22 2031.59,4032.05 2033.31,4019 2031.59,4005.95 2026.55,3993.78 2018.54,3983.34 2008.09,3975.33 1995.93,3970.29 1982.87,3968.57 1969.82,3970.29 1957.66,3975.33 1947.21,3983.34 1939.2,3993.78 1934.16,4005.95
  pour cut-out: 2269.29,4019 2271.01,4032.05 2276.05,4044.22 2284.06,4054.66 2294.51,4062.67 2306.67,4067.71 2319.72,4069.43 2332.78,4067.71 2344.94,4062.67 2355.39,4054.66 2363.4,4044.22 2368.44,4032.05 2370.16,4019 2368.44,4005.95 2363.4,3993.78 2355.39,3983.34 2344.94,3975.33 2332.78,3970.29 2319.72,3968.57 2306.67,3970.29 2294.51,3975.33 2284.06,3983.34 2276.05,3993.78 2271.01,4005.95
  pour cut-out: 2529.29,4019 2531.01,4032.05 2536.05,4044.22 2544.06,4054.66 2554.51,4062.67 2566.67,4067.71 2579.72,4069.43 2592.78,4067.71 2604.94,4062.67 2615.39,4054.66 2623.4,4044.22 2628.44,4032.05 2630.16,4019 2628.44,4005.95 2623.4,3993.78 2615.39,3983.34 2604.94,3975.33 2592.78,3970.29 2579.72,3968.57 2566.67,3970.29 2554.51,3975.33 2544.06,3983.34 2536.05,3993.78 2531.01,4005.95
  pour cut-out: 2866.14,4019 2867.86,4032.05 2872.9,4044.22 2880.91,4054.66 2891.36,4062.67 2903.52,4067.71 2916.57,4069.43 2929.63,4067.71 2941.79,4062.67 2952.24,4054.66 2960.25,4044.22 2965.29,4032.05 2967.01,4019 2965.29,4005.95 2960.25,3993.78 2952.24,3983.34 2941.79,3975.33 2929.63,3970.29 2916.57,3968.57 2903.52,3970.29 2891.36,3975.33 2880.91,3983.34 2872.9,3993.78 2867.86,4005.95
  pour cut-out: 4968.9,2067.19 4970.62,2080.25 4975.66,2092.41 4983.67,2102.85 4994.12,2110.87 5006.28,2115.91 5019.33,2117.63 5032.38,2115.91 5044.55,2110.87 5054.99,2102.85 5063.01,2092.41 5068.05,2080.25 5069.76,2067.19 5068.05,2054.14 5063.01,2041.98 5054.99,2031.53 5044.55,2023.52 5032.38,2018.48 5019.33,2016.76 5006.28,2018.48 4994.12,2023.52 4983.67,2031.53 4975.66,2041.98 4970.62,2054.14
  pour cut-out: 4968.9,1730.34 4970.62,1743.4 4975.66,1755.56 4983.67,1766 4994.12,1774.02 5006.28,1779.06 5019.33,1780.78 5032.38,1779.06 5044.55,1774.02 5054.99,1766 5063.01,1755.56 5068.05,1743.4 5069.76,1730.34 5068.05,1717.29 5063.01,1705.13 5054.99,1694.68 5044.55,1686.67 5032.38,1681.63 5019.33,1679.91 5006.28,1681.63 4994.12,1686.67 4983.67,1694.68 4975.66,1705.13 4970.62,1717.29
  pour cut-out: 4968.9,1420.34 4970.62,1433.4 4975.66,1445.56 4983.67,1456 4994.12,1464.02 5006.28,1469.06 5019.33,1470.78 5032.38,1469.06 5044.55,1464.02 5054.99,1456 5063.01,1445.56 5068.05,1433.4 5069.76,1420.34 5068.05,1407.29 5063.01,1395.13 5054.99,1384.68 5044.55,1376.67 5032.38,1371.63 5019.33,1369.91 5006.28,1371.63 4994.12,1376.67 4983.67,1384.68 4975.66,1395.13 4970.62,1407.29
  pour cut-out: 4968.9,1083.49 4970.62,1096.55 4975.66,1108.71 4983.67,1119.15 4994.12,1127.17 5006.28,1132.21 5019.33,1133.93 5032.38,1132.21 5044.55,1127.17 5054.99,1119.15 5063.01,1108.71 5068.05,1096.55 5069.76,1083.49 5068.05,1070.44 5063.01,1058.28 5054.99,1047.83 5044.55,1039.82 5032.38,1034.78 5019.33,1033.06 5006.28,1034.78 4994.12,1039.82 4983.67,1047.83 4975.66,1058.28 4970.62,1070.44
  pour cut-out: 4299.24,479 4300.96,492.05 4306,504.22 4314.01,514.66 4324.46,522.67 4336.62,527.71 4349.68,529.43 4362.73,527.71 4374.89,522.67 4385.34,514.66 4393.35,504.22 4398.39,492.05 4400.11,479 4398.39,465.95 4393.35,453.78 4385.34,443.34 4374.89,435.33 4362.73,430.29 4349.68,428.57 4336.62,430.29 4324.46,435.33 4314.01,443.34 4306,453.78 4300.96,465.95
  pour cut-out: 3962.39,479 3964.11,492.05 3969.15,504.22 3977.16,514.66 3987.61,522.67 3999.77,527.71 4012.83,529.43 4025.88,527.71 4038.04,522.67 4048.49,514.66 4056.5,504.22 4061.54,492.05 4063.26,479 4061.54,465.95 4056.5,453.78 4048.49,443.34 4038.04,435.33 4025.88,430.29 4012.83,428.57 3999.77,430.29 3987.61,435.33 3977.16,443.34 3969.15,453.78 3964.11,465.95
  pour cut-out: 3652.39,479 3654.11,492.05 3659.15,504.22 3667.16,514.66 3677.61,522.67 3689.77,527.71 3702.83,529.43 3715.88,527.71 3728.04,522.67 3738.49,514.66 3746.5,504.22 3751.54,492.05 3753.26,479 3751.54,465.95 3746.5,453.78 3738.49,443.34 3728.04,435.33 3715.88,430.29 3702.83,428.57 3689.77,430.29 3677.61,435.33 3667.16,443.34 3659.15,453.78 3654.11,465.95
  pour cut-out: 3315.54,479 3317.26,492.05 3322.3,504.22 3330.31,514.66 3340.76,522.67 3352.92,527.71 3365.98,529.43 3379.03,527.71 3391.19,522.67 3401.64,514.66 3409.65,504.22 3414.69,492.05 3416.41,479 3414.69,465.95 3409.65,453.78 3401.64,443.34 3391.19,435.33 3379.03,430.29 3365.98,428.57 3352.92,430.29 3340.76,435.33 3330.31,443.34 3322.3,453.78 3317.26,465.95
  pour cut-out: 2358.69,479 2360.41,492.05 2365.45,504.22 2373.46,514.66 2383.91,522.67 2396.07,527.71 2409.13,529.43 2422.18,527.71 2434.34,522.67 2444.79,514.66 2452.8,504.22 2457.84,492.05 2459.56,479 2457.84,465.95 2452.8,453.78 2444.79,443.34 2434.34,435.33 2422.18,430.29 2409.13,428.57 2396.07,430.29 2383.91,435.33 2373.46,443.34 2365.45,453.78 2360.41,465.95
  pour cut-out: 2021.84,479 2023.56,492.05 2028.6,504.22 2036.61,514.66 2047.06,522.67 2059.22,527.71 2072.28,529.43 2085.33,527.71 2097.49,522.67 2107.94,514.66 2115.95,504.22 2120.99,492.05 2122.71,479 2120.99,465.95 2115.95,453.78 2107.94,443.34 2097.49,435.33 2085.33,430.29 2072.28,428.57 2059.22,430.29 2047.06,435.33 2036.61,443.34 2028.6,453.78 2023.56,465.95
  pour cut-out: 1711.84,479 1713.56,492.05 1718.6,504.22 1726.61,514.66 1737.06,522.67 1749.22,527.71 1762.28,529.43 1775.33,527.71 1787.49,522.67 1797.94,514.66 1805.95,504.22 1810.99,492.05 1812.71,479 1810.99,465.95 1805.95,453.78 1797.94,443.34 1787.49,435.33 1775.33,430.29 1762.28,428.57 1749.22,430.29 1737.06,435.33 1726.61,443.34 1718.6,453.78 1713.56,465.95
  pour cut-out: 1374.99,479 1376.71,492.05 1381.75,504.22 1389.76,514.66 1400.21,522.67 1412.37,527.71 1425.43,529.43 1438.48,527.71 1450.64,522.67 1461.09,514.66 1469.1,504.22 1474.14,492.05 1475.86,479 1474.14,465.95 1469.1,453.78 1461.09,443.34 1450.64,435.33 1438.48,430.29 1425.43,428.57 1412.37,430.29 1400.21,435.33 1389.76,443.34 1381.75,453.78 1376.71,465.95
  pour cut-out: 1064.99,479 1066.71,492.05 1071.75,504.22 1079.76,514.66 1090.21,522.67 1102.37,527.71 1115.43,529.43 1128.48,527.71 1140.64,522.67 1151.09,514.66 1159.1,504.22 1164.14,492.05 1165.86,479 1164.14,465.95 1159.1,453.78 1151.09,443.34 1140.64,435.33 1128.48,430.29 1115.43,428.57 1102.37,430.29 1090.21,435.33 1079.76,443.34 1071.75,453.78 1066.71,465.95
  pour cut-out: 728.14,479 729.86,492.05 734.9,504.22 742.91,514.66 753.36,522.67 765.52,527.71 778.58,529.43 791.63,527.71 803.79,522.67 814.24,514.66 822.25,504.22 827.29,492.05 829.01,479 827.29,465.95 822.25,453.78 814.24,443.34 803.79,435.33 791.63,430.29 778.58,428.57 765.52,430.29 753.36,435.33 742.91,443.34 734.9,453.78 729.86,465.95
  pour cut-out: 429.57,555.17 431.29,568.23 436.33,580.39 444.34,590.84 454.78,598.85 466.95,603.89 480,605.61 493.05,603.89 505.22,598.85 515.66,590.84 523.67,580.39 528.71,568.23 530.43,555.17 528.71,542.12 523.67,529.96 515.66,519.51 505.22,511.5 493.05,506.46 480,504.74 466.95,506.46 454.78,511.5 444.34,519.51 436.33,529.96 431.29,542.12
  pour cut-out: 429.57,892.02 431.29,905.08 436.33,917.24 444.34,927.69 454.78,935.7 466.95,940.74 480,942.46 493.05,940.74 505.22,935.7 515.66,927.69 523.67,917.24 528.71,905.08 530.43,892.02 528.71,878.97 523.67,866.81 515.66,856.36 505.22,848.35 493.05,843.31 480,841.59 466.95,843.31 454.78,848.35 444.34,856.36 436.33,866.81 431.29,878.97
  pour cut-out: 429.57,1488.87 431.29,1501.93 436.33,1514.09 444.34,1524.54 454.78,1532.55 466.95,1537.59 480,1539.31 493.05,1537.59 505.22,1532.55 515.66,1524.54 523.67,1514.09 528.71,1501.93 530.43,1488.87 528.71,1475.82 523.67,1463.66 515.66,1453.21 505.22,1445.2 493.05,1440.16 480,1438.44 466.95,1440.16 454.78,1445.2 444.34,1453.21 436.33,1463.66 431.29,1475.82
  pour cut-out: 429.57,2345.72 431.29,2358.78 436.33,2370.94 444.34,2381.39 454.78,2389.4 466.95,2394.44 480,2396.16 493.05,2394.44 505.22,2389.4 515.66,2381.39 523.67,2370.94 528.71,2358.78 530.43,2345.72 528.71,2332.67 523.67,2320.51 515.66,2310.06 505.22,2302.05 493.05,2297.01 480,2295.29 466.95,2297.01 454.78,2302.05 444.34,2310.06 436.33,2320.51 431.29,2332.67
  pour cut-out: 429.57,2682.57 431.29,2695.63 436.33,2707.79 444.34,2718.24 454.78,2726.25 466.95,2731.29 480,2733.01 493.05,2731.29 505.22,2726.25 515.66,2718.24 523.67,2707.79 528.71,2695.63 530.43,2682.57 528.71,2669.52 523.67,2657.36 515.66,2646.91 505.22,2638.9 493.05,2633.86 480,2632.14 466.95,2633.86 454.78,2638.9 444.34,2646.91 436.33,2657.36 431.29,2669.52
  pour cut-out: 429.57,1152.02 431.29,1165.08 436.33,1177.24 444.34,1187.69 454.78,1195.7 466.95,1200.74 480,1202.46 493.05,1200.74 505.22,1195.7 515.66,1187.69 523.67,1177.24 528.71,1165.08 530.43,1152.02 528.71,1138.97 523.67,1126.81 515.66,1116.36 505.22,1108.35 493.05,1103.31 480,1101.59 466.95,1103.31 454.78,1108.35 444.34,1116.36 436.33,1126.81 431.29,1138.97
  pour cut-out: 2433.77,2237 2433.77,2010.95 2440.86,2003.86 2664.24,2003.86 2673.12,2012.75 2673.12,2230.78 2662.01,2241.89 2438.7,2241.89
  pour cut-out: 3986.35,3034.57 3986.35,3028.19 3979.81,3034.74 3977.31,3034.74
  pour cut-out: 3948.91,2914.43 3948.91,2884.55 3939.1,2874.74 3879.31,2874.74 3870.31,2883.74 3870.3,2918.9 3879.35,2927.94 3935.4,2927.94
  pour cut-out: 3506.22,3252.57 3506.22,3224.21 3520.39,3210.04 3564.64,3210.04 3571.15,3216.55 3571.15,3266.16 3558.71,3278.61 3532.25,3278.61
  pour cut-out: 5333.96,3436.89 5335.68,3449.94 5340.72,3462.1 5348.73,3472.55 5359.18,3480.56 5371.34,3485.6 5384.39,3487.32 5397.45,3485.6 5409.61,3480.56 5420.05,3472.55 5428.07,3462.1 5433.11,3449.94 5434.83,3436.89 5433.11,3423.83 5428.07,3411.67 5420.05,3401.22 5409.61,3393.21 5397.45,3388.17 5384.39,3386.45 5371.34,3388.17 5359.18,3393.21 5348.73,3401.22 5340.72,3411.67 5335.68,3423.83
  pour cut-out: 3556.04,3203.62 3477.79,3203.62 3472,3197.83 3472,3160.54 3477.04,3155.92 3555,3155.92 3555,3147.1 3467.93,3147.1 3460.21,3154.81 3460.21,3205.37 3469.03,3214.18 3557.02,3214.18
  pour cut-out: 967.1,2797.66 942.15,2772.71 942.15,2769.59 995.35,2716.4 1059.81,2716.4 1067.1,2723.69 1067.1,2787.42 1057.25,2797.27 974.94,2797.27
  pour cut-out: 2310.49,2160.97 cw(c2310.49,2175.97) 2295.49,2175.97 cw(c2310.49,2175.97) 2310.49,2190.97 cw(c2310.49,2175.97) 2325.49,2175.97 cw(c2310.49,2175.97)
  pour cut-out: 2138.36,2180.07 cw(c2138.36,2195.07) 2123.36,2195.07 cw(c2138.36,2195.07) 2138.36,2210.07 cw(c2138.36,2195.07) 2153.36,2195.07 cw(c2138.36,2195.07)
  pour cut-out: 3037.13,2179.63 cw(c3037.13,2194.63) 3022.13,2194.63 cw(c3037.13,2194.63) 3037.13,2209.63 cw(c3037.13,2194.63) 3052.13,2194.63 cw(c3037.13,2194.63)
  pour cut-out: 2780.69,2112.34 cw(c2780.69,2127.34) 2765.69,2127.34 cw(c2780.69,2127.34) 2780.69,2142.34 cw(c2780.69,2127.34) 2795.69,2127.34 cw(c2780.69,2127.34)
  pour cut-out: 2785.08,2036.6 cw(c2785.08,2051.6) 2770.08,2051.6 cw(c2785.08,2051.6) 2785.08,2066.6 cw(c2785.08,2051.6) 2800.08,2051.6 cw(c2785.08,2051.6)
  pour cut-out: 2952.65,2003.85 cw(c2952.65,2018.85) 2937.65,2018.85 cw(c2952.65,2018.85) 2952.65,2033.85 cw(c2952.65,2018.85) 2967.65,2018.85 cw(c2952.65,2018.85)
  text "1" at 4572.44,637.86 h100
  text ".Layer_Name" at 577,-858.49 h60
